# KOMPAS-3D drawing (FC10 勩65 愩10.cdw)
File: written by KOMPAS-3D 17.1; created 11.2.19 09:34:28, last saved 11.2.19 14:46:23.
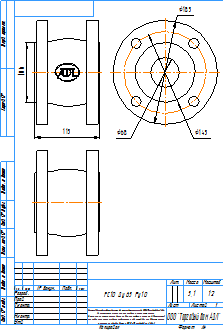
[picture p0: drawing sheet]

Sheet 1: A4, portrait

Title block, sheet 1: name: FC10 Ду65 Ру10; mass: 5,1; sheets: 1; sheet format: A4; stored path: \\adlc.lan\data\АДЛ_ПКД\3D-модели\ADL production\Гибкие вставки серии FC\FC10\KOMPAS 2D\FC10 Ду65 Ру10.cdw

Views: Вид 1
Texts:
  kka
  adl
  Рама для чертежей
  Лит-Масса-Масштаб
  Материал-Предприятие
  Масштаб
  Изм.
  Лист
  № докум.
  Подп.
  Дата
  Лит.
  Разраб.
  Пров.
  Т.контр.
  Листов
  Внимание! Данный продукт является объектом авторского права ООО «Торговый Дом АДЛ».
  Запрещается изменение, копирование, распространение
  (в том числе путем копирования на другие сайты и ресурсы в Интернете)
  или любое иное использование информации и объектов без предварительного
  согласия правообладателя (ООО «Торговый Дом АДЛ»).
  Н.контр.
  Утв.
  ООО "Торговый дом АДЛ"
  Изменение
  Номер документа
  Подпись
  Обозначение документа
  Наименование изделия
  Масса изделия по ГОСТ 2.109-73
  Порядковый номер листа
  Общее количество листов в документе
  Характер работы, выполненной лицом, подписавшим документ
  Наименование или индекс предприятия, выпускающего документ
  Инв. № подл.
  Подп. и дата
  Взам. инв. №
  Инв. № дубл.
  Инвентарный номер подлинника по ГОСТ 2.501-68
  Подпись принявшего подлинник в отдел технической документации
  Инвентарный номер подлинника, взамен которого выпущен данный подлинник
  Инвентарный номер дубликата по ГОСТ 2.502-68
  Подпись принявшего дубликат в отдел технической документации
  Справ. №
  Перв. примен.
  Обозначение документа, взамен или на основании которого выпущен данный документ
  Обозначение документа, в котором впервые записан данный документ
  Подпись лица, копировавшего чертеж
  Обозначение формата листа
  !Рама для чертежа
Dimensions and other numbers on the sheet: 115; 106; 68; 145; 185; 1:2; 1; 5,1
